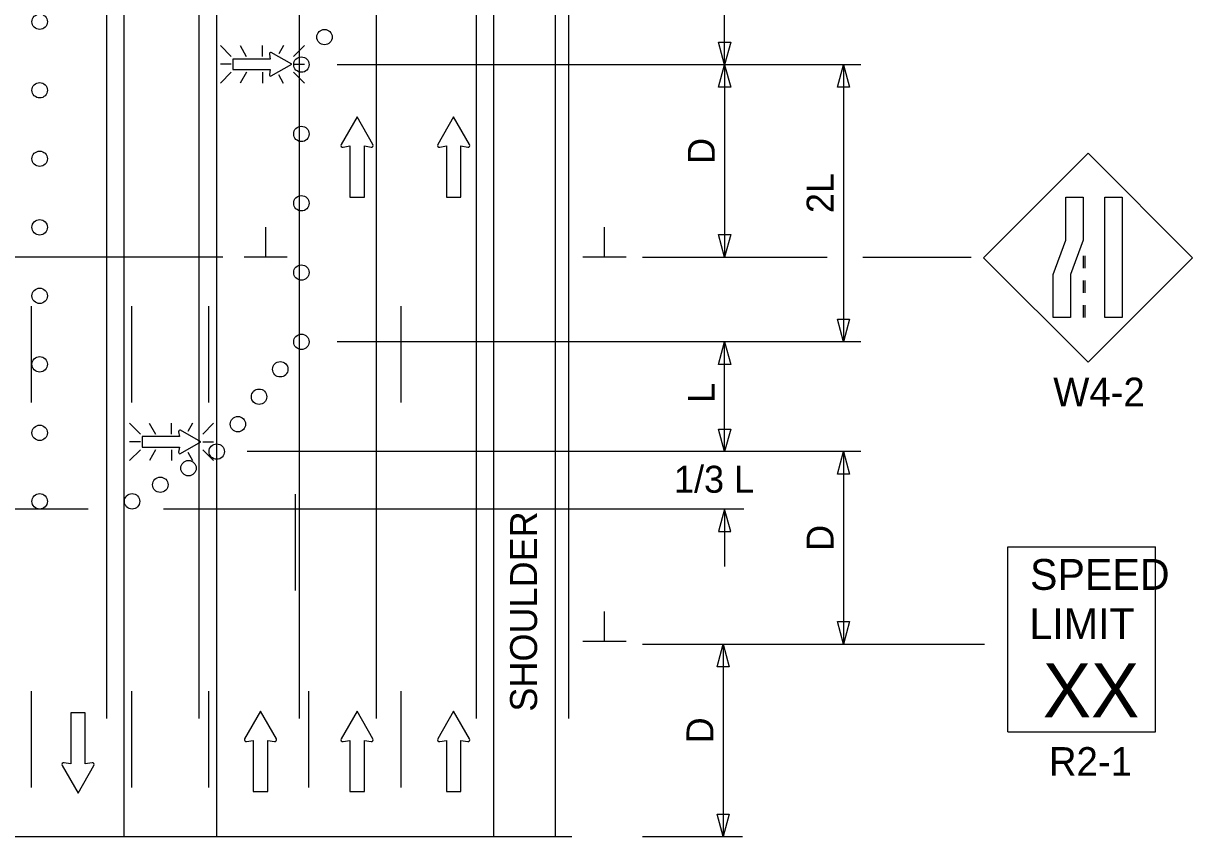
# Model space of a CAD drawing. Extents: x 16730 to 19504, y 5662 to 6979.
# Drawn here: x 16979.7 to 17283.3, y 6101 to 6312.2 of the extents above; entities that cross this region are included whole.
import ezdxf

# ---------------------------------------------------------------- set-up
doc = ezdxf.new("R2010")
doc.units = 0
for name, color, linetype in [('ALI_LEGAL_EX', 7, 'Continuous'), ('MT_SCRATCH_LEVEL_E', 7, 'Continuous'), ('PAVT_EDGE_EX', 7, 'Continuous'), ('TRAFFIC_SIGNS_PR', 7, 'Continuous'), ('TYPICAL_TEXT_DIMEN_PR', 7, 'Continuous')]:
    doc.layers.add(name, color=color, linetype=linetype)

msp = doc.modelspace()

# ---------------------------------------------------------------- linework, layer by layer
at = {"layer": 'ALI_LEGAL_EX'}
for p, q in [((17001.36, 6131.68), (17001.36, 6928.96)), ((17001.36, 6131.68), (17001.36, 6928.96)), ((17025.36, 6131.68), (17025.36, 6928.96)), ((17025.36, 6131.68), (17025.36, 6928.96)), ((17051.36, 6131.68), (17051.36, 6928.96)), ((17051.36, 6131.68), (17051.36, 6928.96)), ((17071.36, 6131.68), (17071.36, 6928.96)), ((17071.36, 6131.68), (17071.36, 6928.96)), ((17097.36, 6131.68), (17097.36, 6928.96)), ((17097.36, 6131.68), (17097.36, 6928.96)), ((17121.36, 6131.68), (17121.36, 6928.96)), ((17121.36, 6131.68), (17121.36, 6928.96))]:
    msp.add_line(p, q, dxfattribs=at)
for points in [[(16981.81, 6213.81), (16981.81, 6238.81)], [(17007.81, 6213.81), (17007.81, 6238.81)], [(17027.81, 6213.81), (17027.81, 6238.81)], [(17077.81, 6213.81), (17077.81, 6238.81)], [(16981.81, 6113.81), (16981.81, 6138.81)], [(17007.81, 6113.81), (17007.81, 6138.81)], [(17027.81, 6113.81), (17027.81, 6138.81)], [(17053.81, 6113.81), (17053.81, 6138.81)], [(17077.81, 6113.81), (17077.81, 6138.81)]]:
    msp.add_lwpolyline(points, dxfattribs=at)
at = {"layer": 'MT_SCRATCH_LEVEL_E'}
for p, q in [((17066.34, 6288.01), (17062.23, 6280.77)), ((17066.34, 6288.01), (17062.23, 6280.77)), ((17070.48, 6280.77), (17066.34, 6288.01)), ((17070.48, 6280.77), (17066.34, 6288.01)), ((17091.43, 6288.01), (17087.32, 6280.77)), ((17091.43, 6288.01), (17087.32, 6280.77)), ((17095.57, 6280.77), (17091.43, 6288.01)), ((17095.57, 6280.77), (17091.43, 6288.01)), ((17062.71, 6280.09), (17064.49, 6280.4)), ((17062.71, 6280.09), (17064.49, 6280.4)), ((17064.49, 6280.4), (17064.49, 6267.14)), ((17064.49, 6280.4), (17064.49, 6267.14)), ((17068.23, 6267.14), (17068.23, 6280.4)), ((17068.23, 6280.4), (17070.01, 6280.09)), ((17068.23, 6267.14), (17068.23, 6280.4)), ((17068.23, 6280.4), (17070.01, 6280.09)), ((17087.8, 6280.09), (17089.58, 6280.4)), ((17087.8, 6280.09), (17089.58, 6280.4)), ((17089.58, 6280.4), (17089.58, 6267.14)), ((17089.58, 6280.4), (17089.58, 6267.14)), ((17093.32, 6267.14), (17093.32, 6280.4)), ((17093.32, 6280.4), (17095.1, 6280.09)), ((17093.32, 6267.14), (17093.32, 6280.4)), ((17093.32, 6280.4), (17095.1, 6280.09)), ((17064.49, 6267.14), (17068.23, 6267.14)), ((17064.49, 6267.14), (17068.23, 6267.14)), ((17089.58, 6267.14), (17093.32, 6267.14)), ((17089.58, 6267.14), (17093.32, 6267.14)), ((16995.74, 6133.16), (16991.99, 6133.16)), ((16991.99, 6133.16), (16991.99, 6119.9)), ((16995.74, 6133.16), (16991.99, 6133.16)), ((16991.99, 6133.16), (16991.99, 6119.9)), ((16995.74, 6119.9), (16995.74, 6133.16)), ((16995.74, 6119.9), (16995.74, 6133.16)), ((17041.25, 6133.62), (17037.14, 6126.38)), ((17041.25, 6133.62), (17037.14, 6126.38)), ((17045.4, 6126.38), (17041.25, 6133.62)), ((17045.4, 6126.38), (17041.25, 6133.62)), ((17066.34, 6133.62), (17062.23, 6126.38)), ((17066.34, 6133.62), (17062.23, 6126.38)), ((17070.48, 6126.38), (17066.34, 6133.62)), ((17070.48, 6126.38), (17066.34, 6133.62)), ((17091.43, 6133.62), (17087.32, 6126.38)), ((17091.43, 6133.62), (17087.32, 6126.38)), ((17095.57, 6126.38), (17091.43, 6133.62)), ((17095.57, 6126.38), (17091.43, 6133.62)), ((17037.62, 6125.69), (17039.4, 6126.01)), ((17037.62, 6125.69), (17039.4, 6126.01)), ((17039.4, 6126.01), (17039.4, 6112.75)), ((17039.4, 6126.01), (17039.4, 6112.75)), ((17043.14, 6112.75), (17043.14, 6126.01)), ((17043.14, 6126.01), (17044.92, 6125.69)), ((17043.14, 6112.75), (17043.14, 6126.01)), ((17043.14, 6126.01), (17044.92, 6125.69)), ((17062.71, 6125.69), (17064.49, 6126.01)), ((17062.71, 6125.69), (17064.49, 6126.01)), ((17064.49, 6126.01), (17064.49, 6112.75)), ((17064.49, 6126.01), (17064.49, 6112.75)), ((17068.23, 6112.75), (17068.23, 6126.01)), ((17068.23, 6126.01), (17070.01, 6125.69)), ((17068.23, 6112.75), (17068.23, 6126.01)), ((17068.23, 6126.01), (17070.01, 6125.69)), ((17087.8, 6125.69), (17089.58, 6126.01)), ((17087.8, 6125.69), (17089.58, 6126.01)), ((17089.58, 6126.01), (17089.58, 6112.75)), ((17089.58, 6126.01), (17089.58, 6112.75)), ((17093.32, 6112.75), (17093.32, 6126.01)), ((17093.32, 6126.01), (17095.1, 6125.69)), ((17093.32, 6112.75), (17093.32, 6126.01)), ((17093.32, 6126.01), (17095.1, 6125.69)), ((16989.74, 6119.53), (16993.89, 6112.29)), ((16989.74, 6119.53), (16993.89, 6112.29)), ((16991.99, 6119.9), (16990.22, 6120.22)), ((16991.99, 6119.9), (16990.22, 6120.22)), ((16993.89, 6112.29), (16998, 6119.53)), ((16993.89, 6112.29), (16998, 6119.53)), ((16997.51, 6120.22), (16995.74, 6119.9)), ((16997.51, 6120.22), (16995.74, 6119.9)), ((17039.4, 6112.75), (17043.14, 6112.75)), ((17039.4, 6112.75), (17043.14, 6112.75)), ((17064.49, 6112.75), (17068.23, 6112.75)), ((17064.49, 6112.75), (17068.23, 6112.75)), ((17089.58, 6112.75), (17093.32, 6112.75)), ((17089.58, 6112.75), (17093.32, 6112.75))]:
    msp.add_line(p, q, dxfattribs=at)
for centre, start, end in [((17062.63, 6280.54), 150.4248, 279.9638), ((17062.63, 6280.54), 150.4248, 279.9638), ((17070.07, 6280.55), 260.0362, 29.7731), ((17070.07, 6280.55), 260.0362, 29.7731), ((17087.72, 6280.54), 150.4248, 279.9638), ((17087.72, 6280.54), 150.4248, 279.9638), ((17095.16, 6280.55), 260.0362, 29.7731), ((17095.16, 6280.55), 260.0362, 29.7731), ((17037.54, 6126.15), 150.4248, 279.9638), ((17037.54, 6126.15), 150.4248, 279.9638), ((17044.99, 6126.15), 260.0362, 29.7731), ((17044.99, 6126.15), 260.0362, 29.7731), ((17062.63, 6126.15), 150.4248, 279.9638), ((17062.63, 6126.15), 150.4248, 279.9638), ((17070.07, 6126.15), 260.0362, 29.7731), ((17070.07, 6126.15), 260.0362, 29.7731), ((17087.72, 6126.15), 150.4248, 279.9638), ((17087.72, 6126.15), 150.4248, 279.9638), ((17095.16, 6126.15), 260.0362, 29.7731), ((17095.16, 6126.15), 260.0362, 29.7731), ((16990.15, 6119.76), 80.0362, 209.7731), ((16990.15, 6119.76), 80.0362, 209.7731), ((16997.59, 6119.76), 330.4248, 99.9638), ((16997.59, 6119.76), 330.4248, 99.9638)]:
    msp.add_arc(centre, 0.463, start, end, dxfattribs=at)
at = {"layer": 'PAVT_EDGE_EX'}
for p, q in [((17005.81, 6869.88), (17005.81, 6101.02)), ((17029.81, 6869.88), (17029.81, 6101.02)), ((17101.81, 6869.88), (17101.81, 6101.02)), ((17117.81, 6869.88), (17117.81, 6101.02))]:
    msp.add_line(p, q, dxfattribs=at)
for points in [[(17025.36, 6164.93), (17025.36, 6189.93)], [(17050.36, 6164.93), (17050.36, 6189.93)]]:
    msp.add_lwpolyline(points, dxfattribs=at)
at = {"layer": 'TRAFFIC_SIGNS_PR'}
for p, q in [((17033.66, 6303.64), (17030.84, 6306.46)), ((17035.96, 6306.46), (17037.58, 6303.64)), ((17041.74, 6303.64), (17041.74, 6306.46)), ((17047.21, 6306.46), (17046.01, 6304.36)), ((17052.65, 6306.46), (17049.83, 6303.64)), ((17033.66, 6301.61), (17030.84, 6301.61)), ((17049.83, 6301.61), (17052.65, 6301.61)), ((17033.66, 6299.57), (17030.84, 6296.75)), ((17037.61, 6299.57), (17035.98, 6296.75)), ((17041.74, 6299.57), (17041.74, 6296.75)), ((17045.93, 6298.94), (17047.19, 6296.75)), ((17052.65, 6296.76), (17049.83, 6299.57)), ((17256.19, 6278.53), (17229.04, 6251.38)), ((17283.35, 6251.38), (17256.19, 6278.53)), ((17229.04, 6251.38), (17256.19, 6224.23)), ((17254.95, 6251.87), (17254.95, 6248.67)), ((17255.35, 6251.87), (17255.35, 6248.67)), ((17256.19, 6224.23), (17283.35, 6251.38)), ((17254.95, 6245.47), (17254.95, 6242.27)), ((17255.35, 6245.47), (17255.35, 6242.27)), ((17254.95, 6239.07), (17254.95, 6235.87)), ((17255.35, 6239.07), (17255.35, 6235.87)), ((17010.08, 6205.55), (17007.26, 6208.38)), ((17012.38, 6208.37), (17014, 6205.55)), ((17018.16, 6205.55), (17018.16, 6208.37)), ((17023.63, 6208.37), (17022.43, 6206.28)), ((17029.07, 6208.37), (17026.25, 6205.55)), ((17010.08, 6203.52), (17007.26, 6203.52)), ((17010.08, 6201.49), (17007.26, 6198.67)), ((17014.03, 6201.49), (17012.4, 6198.67)), ((17018.16, 6201.49), (17018.16, 6198.67)), ((17026.25, 6203.52), (17029.07, 6203.52)), ((17029.07, 6198.67), (17026.25, 6201.49)), ((17022.35, 6200.86), (17023.61, 6198.67)), ((17235.34, 6176.26), (17273.74, 6176.26)), ((17235.34, 6128.26), (17235.34, 6176.26)), ((17273.74, 6128.26), (17273.74, 6176.26)), ((17235.34, 6128.26), (17273.74, 6128.26))]:
    msp.add_line(p, q, dxfattribs=at)
for points in [[(17043.57, 6304.29), (17043.8, 6302.99), (17034.08, 6302.99), (17034.08, 6300.25), (17043.8, 6300.25), (17043.57, 6298.94)], [(17044.07, 6298.59), (17049.38, 6301.61), (17044.07, 6304.65)], [(17019.99, 6206.2), (17020.22, 6204.91), (17010.5, 6204.91), (17010.5, 6202.16), (17020.22, 6202.16), (17019.99, 6200.86)], [(17020.49, 6200.51), (17025.8, 6203.52), (17020.49, 6206.56)]]:
    msp.add_lwpolyline(points, dxfattribs=at)
for points in [[(17254.95, 6267.11), (17254.95, 6255.93), (17251.6, 6247.05), (17251.6, 6235.87), (17247.11, 6235.87), (17247.11, 6247.05), (17250.45, 6255.93), (17250.45, 6267.11)], [(17265.08, 6267.11), (17265.08, 6235.87), (17260.59, 6235.87), (17260.59, 6267.11)]]:
    msp.add_lwpolyline(points, close=True, dxfattribs=at)
for centre in [(16983.91, 6312.67), (17057.88, 6308.68), (17051.88, 6301.54), (16983.91, 6294.87), (17051.88, 6283.53), (16983.91, 6277.08), (17051.88, 6265.53), (16983.91, 6259.28), (17051.88, 6247.53), (16983.91, 6241.49), (17051.88, 6229.53), (16983.91, 6223.69), (17046.39, 6222.4), (17040.89, 6215.28), (17035.39, 6208.15), (16983.91, 6205.9), (17029.9, 6201.02), (17022.57, 6196.72), (17015.24, 6192.41), (16983.91, 6188.1), (17007.91, 6188.1), (17007.91, 6188.1)]:
    msp.add_circle(centre, 2, dxfattribs=at)
for centre, start, end in [((17043.91, 6304.35), 61.4833, 189.9593), ((17043.91, 6298.89), 170.7308, 298.8916), ((17020.33, 6206.26), 61.4833, 189.9593), ((17020.33, 6200.81), 170.7308, 298.8916)]:
    msp.add_arc(centre, 0.341, start, end, dxfattribs=at)
at = {"layer": 'TYPICAL_TEXT_DIMEN_PR'}
for p, q in [((17161.81, 6301.52), (17161.81, 6332.1)), ((17161.81, 6301.52), (17160.24, 6307.39)), ((17160.24, 6307.39), (17161.81, 6307.39)), ((17161.81, 6307.39), (17163.38, 6307.39)), ((17163.38, 6307.39), (17161.81, 6301.52)), ((17197.18, 6301.52), (17061.17, 6301.52)), ((17160.24, 6295.66), (17161.81, 6301.52)), ((17161.81, 6301.52), (17161.81, 6251.52)), ((17161.81, 6301.52), (17163.38, 6295.66)), ((17191.09, 6295.66), (17192.66, 6301.52)), ((17192.66, 6301.52), (17192.66, 6229.53)), ((17192.66, 6301.52), (17194.23, 6295.66)), ((17161.81, 6295.66), (17160.24, 6295.66)), ((17163.38, 6295.66), (17161.81, 6295.66)), ((17192.66, 6295.66), (17191.09, 6295.66)), ((17194.23, 6295.66), (17192.66, 6295.66)), ((17042.61, 6251.52), (17042.61, 6259.31)), ((17130.57, 6251.52), (17130.57, 6259.31)), ((17161.81, 6251.52), (17160.24, 6257.39)), ((17160.24, 6257.39), (17161.81, 6257.39)), ((17161.81, 6257.39), (17163.38, 6257.39)), ((17163.38, 6257.39), (17161.81, 6251.52)), ((17031.52, 6251.52), (16857.53, 6251.52)), ((17048.23, 6251.52), (17036.98, 6251.52)), ((17136.19, 6251.52), (17124.94, 6251.52)), ((17140.44, 6251.52), (17188.45, 6251.52)), ((17197.71, 6251.52), (17225.85, 6251.52)), ((17192.66, 6229.53), (17191.09, 6235.4)), ((17191.09, 6235.4), (17192.66, 6235.4)), ((17192.66, 6235.4), (17194.23, 6235.4)), ((17194.23, 6235.4), (17192.66, 6229.53)), ((17197.18, 6229.53), (17061.17, 6229.53)), ((17160.24, 6223.67), (17161.81, 6229.53)), ((17161.81, 6201.02), (17161.81, 6229.53)), ((17161.81, 6229.53), (17163.38, 6223.67)), ((17161.81, 6223.67), (17160.24, 6223.67)), ((17163.38, 6223.67), (17161.81, 6223.67)), ((17161.81, 6201.02), (17160.24, 6206.89)), ((17160.24, 6206.89), (17161.81, 6206.89)), ((17161.81, 6206.89), (17163.38, 6206.89)), ((17163.38, 6206.89), (17161.81, 6201.02)), ((17197.18, 6201.02), (17037.77, 6201.02)), ((17191.09, 6195.16), (17192.66, 6201.02)), ((17192.66, 6201.02), (17194.23, 6195.16)), ((17192.66, 6201.02), (17192.66, 6151.02)), ((17192.66, 6195.16), (17191.09, 6195.16)), ((17194.23, 6195.16), (17192.66, 6195.16)), ((16996.51, 6186.1), (16868.81, 6186.1)), ((17166.81, 6186.1), (17016.04, 6186.1)), ((17161.81, 6186.1), (17160.24, 6180.24)), ((17161.81, 6186.1), (17161.81, 6171.18)), ((17163.38, 6180.24), (17161.81, 6186.1)), ((17160.24, 6180.24), (17161.81, 6180.24)), ((17161.81, 6180.24), (17163.38, 6180.24)), ((17130.57, 6151.67), (17130.57, 6159.46)), ((17192.66, 6151.02), (17191.09, 6156.89)), ((17191.09, 6156.89), (17192.66, 6156.89)), ((17192.66, 6156.89), (17194.23, 6156.89)), ((17194.23, 6156.89), (17192.66, 6151.02)), ((17136.19, 6151.67), (17124.94, 6151.67)), ((17140.44, 6151.02), (17229.26, 6151.02)), ((17159.87, 6145.16), (17161.44, 6151.02)), ((17161.44, 6151.02), (17161.44, 6101.02)), ((17161.44, 6151.02), (17163.01, 6145.16)), ((17161.44, 6145.16), (17159.87, 6145.16)), ((17163.01, 6145.16), (17161.44, 6145.16)), ((17161.44, 6101.02), (17159.87, 6106.89)), ((17159.87, 6106.89), (17161.44, 6106.89)), ((17161.44, 6106.89), (17163.01, 6106.89)), ((17163.01, 6106.89), (17161.44, 6101.02)), ((16913.51, 6101.02), (17122.11, 6101.02)), ((17140.44, 6101.02), (17166.44, 6101.02))]:
    msp.add_line(p, q, dxfattribs=at)

# ---------------------------------------------------------------- texts
at = {"layer": 'TRAFFIC_SIGNS_PR'}
for s, height, p in [('W4-2', 7.44, (17247.15, 6212.79)), ('SPEED', 8, (17241.11, 6165.12)), ('LIMIT', 8, (17240.95, 6152.32)), ('XX', 14.031, (17244.46, 6132.02)), ('R2-1', 7.44, (17246.02, 6116.82))]:
    msp.add_text(s, height=height, dxfattribs=at).set_placement(p)
at = {"layer": 'TYPICAL_TEXT_DIMEN_PR'}
for s, p in [('D', (17159.25, 6275.74)), ('2L', (17190.1, 6262.97)), ('L', (17159.25, 6213.67)), ('SHOULDER', (17113.09, 6133.49)), ('D', (17190.1, 6175.24)), ('D', (17158.89, 6125.24))]:
    msp.add_text(s, height=7, rotation=90, dxfattribs=at).set_placement(p)
msp.add_text('1/3 L', height=7, dxfattribs=at).set_placement((17148.65, 6190.34))

doc.saveas('drawing.dxf')
